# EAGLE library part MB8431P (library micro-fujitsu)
MICROCONTROLLER/MEMORY DEVICE
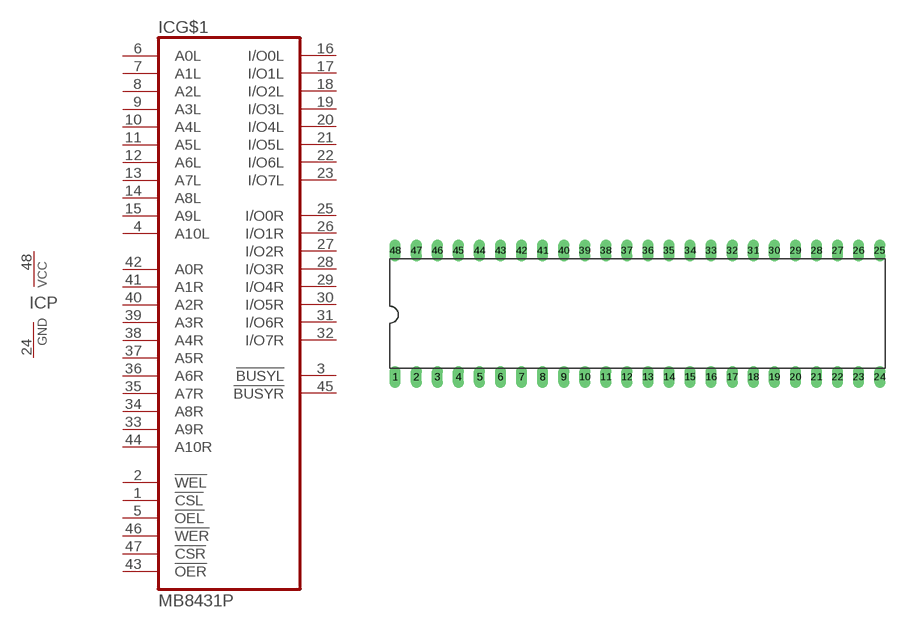
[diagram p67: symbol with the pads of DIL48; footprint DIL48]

Designator prefix IC; gates G$1=MB8431 P=VCC-GND

## MB8431P (OC_FARNELL: unknown; OC_NEWARK: unknown)  [DIL48]
1  G$1:!CSL  in
2  G$1:!WEL  in
3  G$1:!BUSYL  out
4  G$1:A10L  in
5  G$1:!OEL  in
6  G$1:A0L  in
7  G$1:A1L  in
8  G$1:A2L  in
9  G$1:A3L  in
10  G$1:A4L  in
11  G$1:A5L  in
12  G$1:A6L  in
13  G$1:A7L  in
14  G$1:A8L  in
15  G$1:A9L  in
16  G$1:I/O0L
17  G$1:I/O1L
18  G$1:I/O2L
19  G$1:I/O3L
20  G$1:I/O4L
21  G$1:I/O5L
22  G$1:I/O6L
23  G$1:I/O7L
24  P:GND  pwr
25  G$1:I/O0R
26  G$1:I/O1R
27  G$1:I/O2R
28  G$1:I/O3R
29  G$1:I/O4R
30  G$1:I/O5R
31  G$1:I/O6R
32  G$1:I/O7R
33  G$1:A9R  in
34  G$1:A8R  in
35  G$1:A7R  in
36  G$1:A6R  in
37  G$1:A5R  in
38  G$1:A4R  in
39  G$1:A3R  in
40  G$1:A2R  in
41  G$1:A1R  in
42  G$1:A0R  in
43  G$1:!OER  in
44  G$1:A10R  in
45  G$1:!BUSYR  out
46  G$1:!WER  in
47  G$1:!CSR  in
48  P:VCC  pwr

## Footprint DIL48 (pad centres in mm)
Dual In Line Package
drill 0.813 long: 1 -29.21,-7.62; 2 -26.67,-7.62; 3 -24.13,-7.62; 4 -21.59,-7.62; 5 -19.05,-7.62; 6 -16.51,-7.62; 7 -13.97,-7.62; 8 -11.43,-7.62; 9 -8.89,-7.62; 10 -6.35,-7.62; 11 -3.81,-7.62; 12 -1.27,-7.62; 13 1.27,-7.62; 14 3.81,-7.62; 15 6.35,-7.62; 16 8.89,-7.62; 17 11.43,-7.62; 18 13.97,-7.62; 19 16.51,-7.62; 20 19.05,-7.62; 21 21.59,-7.62; 22 24.13,-7.62; 23 26.67,-7.62; 24 29.21,-7.62; 25 29.21,7.62; 26 26.67,7.62; 27 24.13,7.62; 28 21.59,7.62; 29 19.05,7.62; 30 16.51,7.62; 31 13.97,7.62; 32 11.43,7.62; 33 8.89,7.62; 34 6.35,7.62; 35 3.81,7.62; 36 1.27,7.62; 37 -1.27,7.62; 38 -3.81,7.62; 39 -6.35,7.62; 40 -8.89,7.62; 41 -11.43,7.62; 42 -13.97,7.62; 43 -16.51,7.62; 44 -19.05,7.62; 45 -21.59,7.62; 46 -24.13,7.62; 47 -26.67,7.62; 48 -29.21,7.62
